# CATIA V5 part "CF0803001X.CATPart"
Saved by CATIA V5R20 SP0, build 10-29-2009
Part number: FC-1-A-Tooling
Bounding box of the stored display mesh (mm): x -15 to 18, y -380.5 to 35.56, z 0 to 19
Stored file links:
  C:\Users\Raffaele\Desktop\3D X SITO CF\A-TOOLING\FC-1-A-Tooling.CATPart
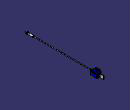
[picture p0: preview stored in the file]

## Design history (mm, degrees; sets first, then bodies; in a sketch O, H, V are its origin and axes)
Set1
  DatumSurface1 to DatumSurface1192
Body1 (main body)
